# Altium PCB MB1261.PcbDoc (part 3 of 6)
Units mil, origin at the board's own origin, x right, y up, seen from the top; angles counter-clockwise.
Board outline 5119.1 x 2638.79 mil, 6 copper layers (TOP, L2_GND, L3_SIG, L4_VCC, L5_GND, BOTTOM), stack 61 mil thick; 336 components, 316 nets, 1358 pads, 871 vias.
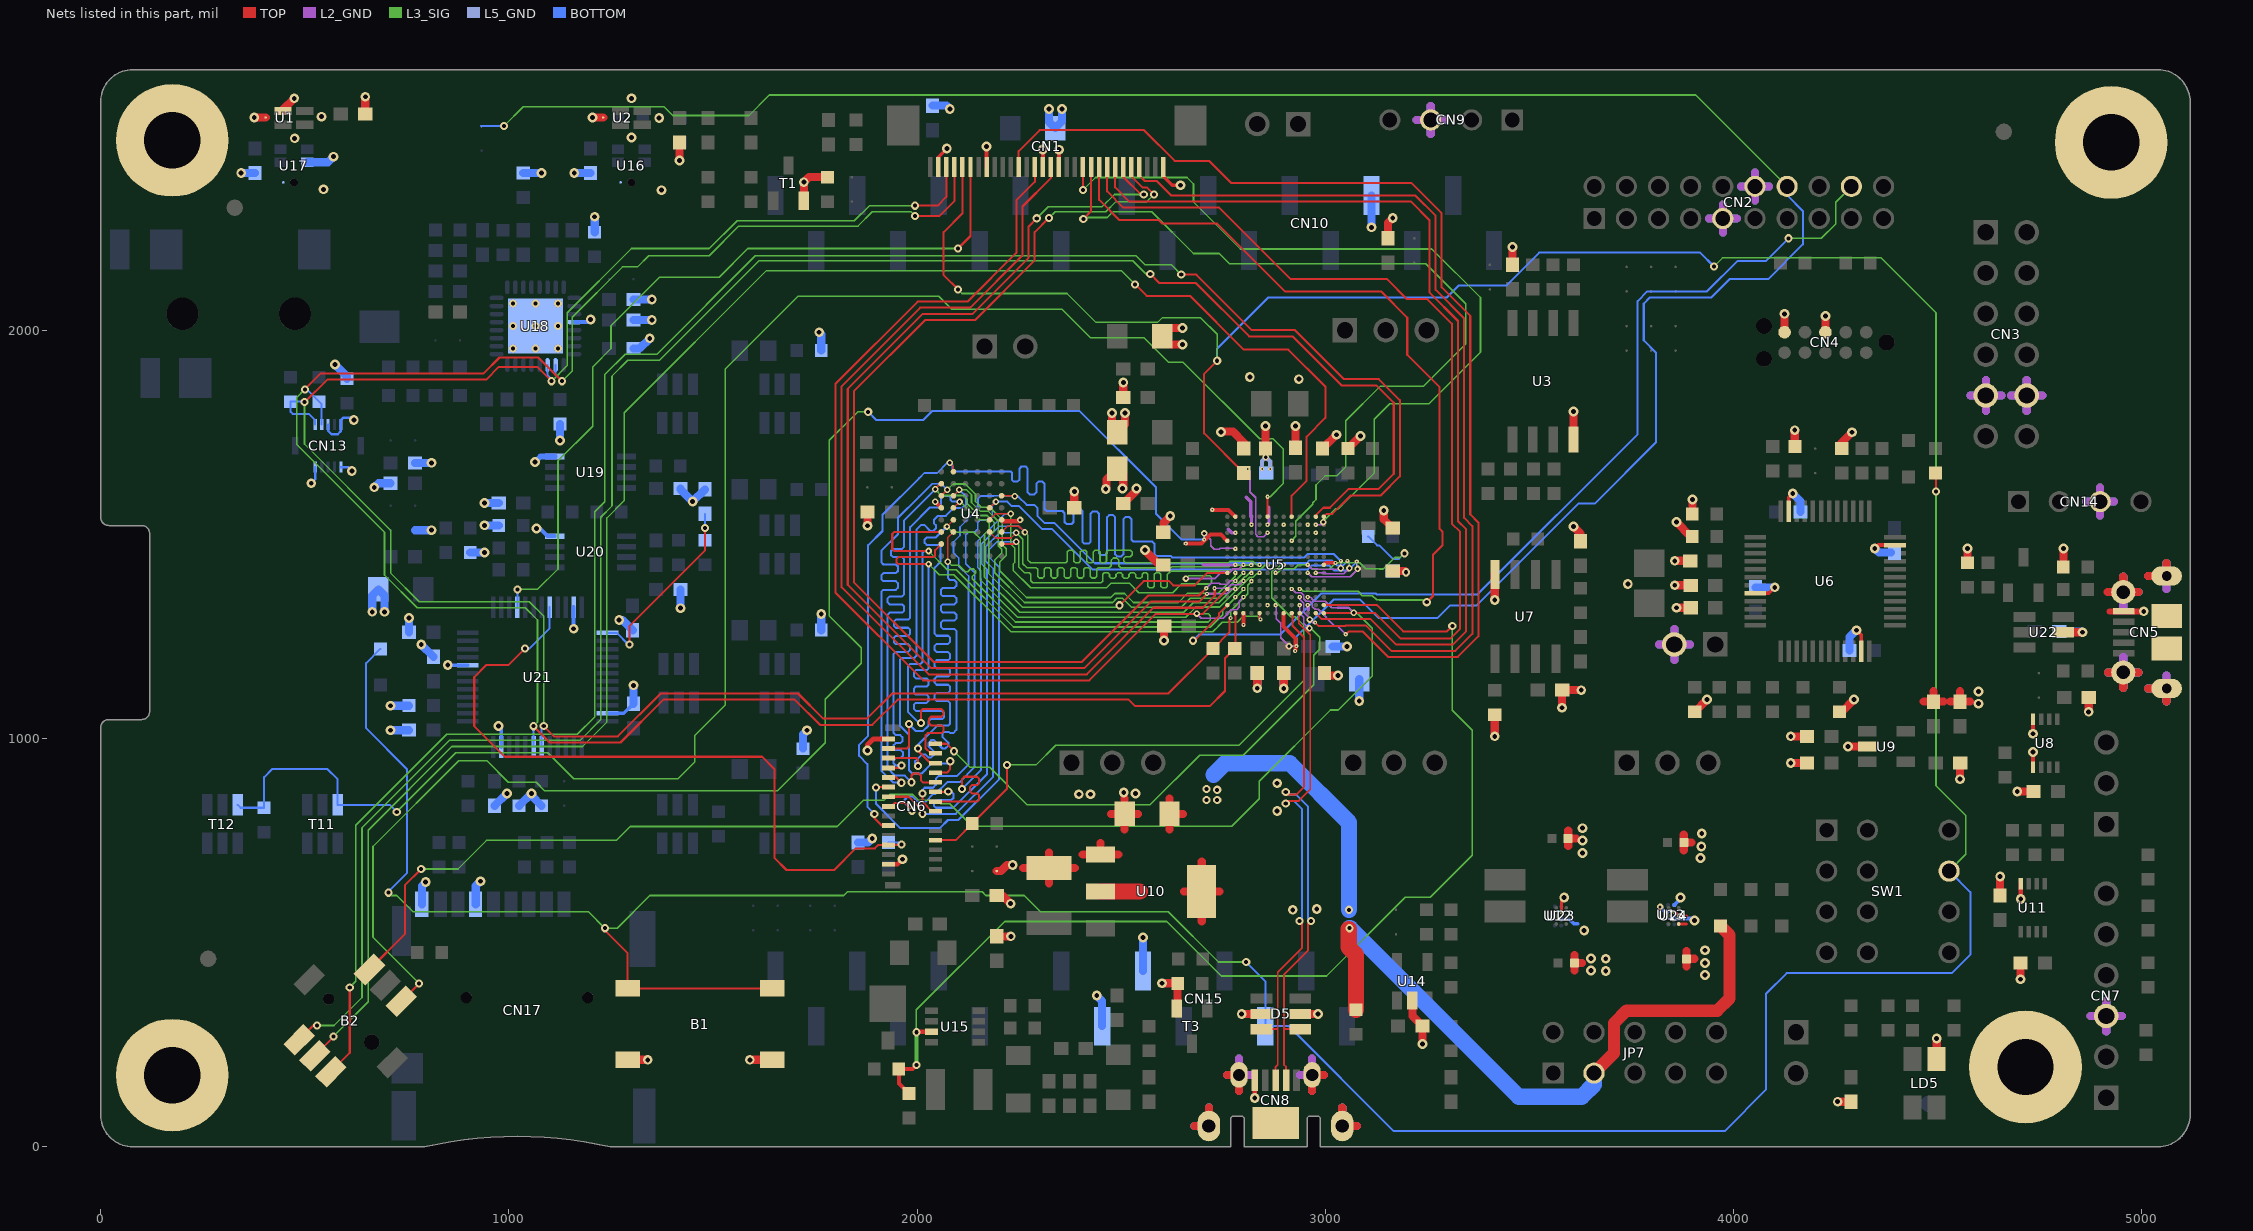
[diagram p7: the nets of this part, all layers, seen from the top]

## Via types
v1: diameter 20, hole 10, TOP to BOTTOM, tented both sides, 317 vias
v2: diameter 24, hole 12, TOP to BOTTOM, tented both sides, 289 vias
v3: diameter 10, hole 4, TOP to L2_GND, tented both sides, 76 vias
v4: diameter 10, hole 4, TOP to L3_SIG, tented both sides, 63 vias
v5: diameter 16, hole 8, L2_GND to L5_GND, tented both sides, 52 vias
v6: diameter 16, hole 8, TOP to BOTTOM, tented both sides, 43 vias
v7: diameter 10, hole 4, L5_GND to BOTTOM, tented both sides, 31 vias

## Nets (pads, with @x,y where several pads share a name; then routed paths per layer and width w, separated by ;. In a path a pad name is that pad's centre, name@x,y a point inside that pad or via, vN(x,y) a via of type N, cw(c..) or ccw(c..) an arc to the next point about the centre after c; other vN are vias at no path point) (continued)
D2: CN6.16 U4.C6 U5.B8 | length 2050.4
  TOP w4: U4.C6@2206.92,1594.29 2237.71,1594.29 v6(2239,1593)
  TOP w5: v1(2013.44,865) 2013.44,844.03 2035.95,821.52 CN6.16@2044.44,821.52
  L2_GND w3.5: v3(2976.53,1405.31) 2999.69,1405.31 3001.94,1403.06 3025.94,1403.06 3026,1403 3045,1403 v5(3059,1417)
  L5_GND w3.5: v7(3054,1434.84) 3058,1430.84 3058,1418 v5(3059,1417)
  BOTTOM w4: 2126,1390 2126,1398 2102,1422 2102,1442 2089,1455 2089,1481 2105,1497 2105,1518 2149,1562 2149,1586.9 2156,1593.9 2187.1,1593.9 2187.2,1594 2238,1594 v6(2239,1593)
  BOTTOM w5: v1(2013.44,865) 2013.44,873.81 2018.63,879 2038.78,879 2046,886.22 2046,901 2052.98,907.98 2097.76,907.98 2126,936.22 2126,1390 ; v6(2239,1593) 2240,1592 2248,1592 2268,1572 2287,1572 2294.5,1564.5 2294.5,1545.5 2312.5,1527.5 2336.72,1527.5 2435.22,1429 2954,1429 2961,1436 3016,1436 3029,1423 3042.16,1423 v7(3054,1434.84)
D3: CN6.15 U4.D5 U5.C8 | length 2179.3
  TOP w4: U4.D5@2177.39,1564.76 2177.76,1564.76 v6(2193,1580)
  TOP w5: CN6.15@1930.26,833.33 1936.38,833.33 1945,841.95 1969.53,841.95 1987.04,824.44 v1(1987.04,822.88)
  L2_GND w3.5: v3(2956.84,1405.31) 2966.59,1395.56 3022.83,1395.56 3022.89,1395.5 3060.49,1395.5 3079,1414 v5(3079,1415)
  L5_GND w3.5: v7(3076.89,1432.88) 3076.89,1416.11 3079,1414 v5(3079,1415)
  BOTTOM w4: 2141,1390 2141,1406 2119,1428 2119,1498 2126,1505 2141,1505 2148,1512 2148,1528 2155,1535 2177,1535 2184,1542 2184,1571 v6(2193,1580)
  BOTTOM w5: v1(1987.04,822.88) 1987.04,823.96 1969,842 1969,849 1978,858 1988,858 2001,845 2020.7,845 2039.7,864 2045,864 2073.98,892.98 2103.98,892.98 2141,930 2141,1390 ; v6(2193,1580) 2221,1580 2232,1569 2249.78,1569 2306.28,1512.5 2330.5,1512.5 2429,1414 2957,1414 2967,1424 3009,1424 3022,1411 3055,1411 v7@3076.77,1432.77 ; v7@3076.78,1432.77 v7(3076.89,1432.88)
D4: CN6.14 U4.E5 U5.L7 | length 1968
  TOP w4: U4.E5@2177.39,1535.24 2192.15,1550 v6(2229,1550)
  TOP w5: CN6.14@2044.44,845.14 2147,845.14 2152,850.14 2152,860.32 2147,865.32 2134,865.32 2129,870.32 2129,880.32 2134,885.32 2147,885.32 2152,890.32 2152,901 2147,906 2115.12,906 2110.12,901 v1(2110.12,876.26)
  L2_GND w3.5: 2766,1407.5 2773.75,1415.25 2789.61,1415.25 v3(2799.36,1425)
  L2_GND w5: v5(2658.48,1391.52) 2729.02,1391.52 2745,1407.5 2766,1407.5
  L3_SIG w4: v6(2229,1550) 2229,1476.2 2239,1466.2 2239,1431 2235,1427 2235,1412 2278,1369 2464,1369 2475,1380 2519.98,1380 2542.98,1357 2626,1357 2647.25,1378.25 2718.25,1378.25 2721,1381 2721,1394.72 2717.39,1398.33 2665.29,1398.33 v5(2658.48,1391.52)
  BOTTOM w4: 2156,1390 2156,1411 2148,1419 2148,1483 2215,1550 v6(2229,1550)
  BOTTOM w5: v1(2110.12,876.26) 2156,922.14 2156,1390
D5: CN6.13 U4.F5 U5.K7 | length 1940.2
  TOP w4: U4.F5@2177.39,1505.71 2192.1,1491 2230,1491 v6(2243,1504)
  TOP w5: CN6.13@1930.26,856.95 1979.3,856.95 2006.62,829.63 2006.62,822.23 v1(2013.45,815.4)
  L3_SIG w4: v6(2243,1504) 2259,1488 2259,1428 2269,1418 2291.08,1418 2295.08,1414 2295.08,1397 2299.08,1393 2307.08,1393 2311.08,1397 2311.08,1414 2315.08,1418 2323.95,1418 2327.95,1414 2327.95,1397 2331.95,1393 2339.95,1393 2343.95,1397 2343.95,1414 2347.95,1418 2355.95,1418 2359.95,1414 2359.95,1397 2363.95,1393 2371.95,1393 2375.95,1397 2375.95,1414 2379.95,1418 2387.95,1418 2391.95,1414 2391.95,1397 2395.95,1393 2403.95,1393 2407.95,1397 2407.95,1414 2411.95,1418 2419.95,1418 2423.95,1414 2423.95,1397 2427.95,1393 2435.95,1393 2439.95,1397 2439.95,1414 2443.95,1418 2470.76,1418 2475.76,1423 2475.76,1437 2480.76,1442 2489,1442 2494,1437 2494,1423 2499,1418 2622.08,1418 2624.08,1420 2764,1420 2768.3,1424.3 v4(2817.7,1424.3)
  BOTTOM w4: 2186,1390 2186,1416 2168,1434 2168,1470 2202,1504 v6(2243,1504)
  BOTTOM w5: v1(2013.45,815.4) 2013.85,815 2094.84,815 2186,906.16 2186,1390
D6: CN6.12 U4.F6 U5.J7 | length 1947.9
  TOP w4: U4.F6@2206.92,1505.71 2221.21,1520 2249.03,1520 v6@2260,1509.03
  TOP w5: CN6.12@2044.44,868.76 2075.23,868.76 v1(2076.16,869.69) ; v6@2260,1509.03 v6(2263.98,1505.05)
  L3_SIG w3.5: 2797,1434 2812.91,1434 2812.96,1434.05 2822.48,1434.05 2831.53,1425 v4(2838.73,1425)
  L3_SIG w4: v6(2263.98,1505.05) 2271,1498.03 2271,1437 2278,1430 2363.76,1430 2367.76,1434 2367.76,1457 2371.76,1461 2379.76,1461 2383.76,1457 2383.76,1434 2387.76,1430 2395.76,1430 2399.76,1434 2399.76,1457 2403.76,1461 2411.76,1461 2415.76,1457 2415.76,1434 2419.76,1430 2427.76,1430 2431.76,1434 2431.76,1457 2435.76,1461 2443.76,1461 2447.76,1457 2447.76,1434 2451.76,1430 2459.76,1430 2463.76,1434 2463.76,1457 2467.76,1461 2522.36,1461 2527,1456.36 2527,1449.8 2522.36,1445.16 2510.44,1445.16 2506,1440.72 2506,1434.44 2510.44,1430 2762.68,1430 2766.68,1434 2797,1434
  BOTTOM w4: 2171,1390 2171,1414 2158,1427 2158,1477 2201,1520 2249.03,1520 v6@2260,1509.03
  BOTTOM w5: v1(2076.16,869.69) 2084,869.69 2089,864.69 2089,854 2084,849 2045.92,849 2040.92,844 2040.92,835 2045.92,830 2088.62,830 2171,912.38 2171,1390 ; v6@2260,1509.03 v6(2263.98,1505.05)
D7: CN6.11 U4.G6 U5.H7 | length 2046.5
  TOP w4: U4.G6@2206.92,1476.18 2237.18,1476.18 v6(2243,1482)
  TOP w5: v1(1899.26,880) 1899.83,880.57 CN6.11@1930.26,880.57
  L3_SIG w3.5: 2617.1,1406 2621.1,1410 2767,1410 2773,1416 2811.51,1416 2812.96,1414.55 2821.04,1414.55 2821.55,1415.06 2843.06,1415.06 2853,1425 v4(2858.41,1425)
  L3_SIG w4: v6(2243,1482) 2249,1476 2249,1420 2263,1406 2274.32,1406 2278.32,1402 2278.32,1386 2283.32,1381 2450.32,1381 2454.32,1385 2454.32,1402 2458.32,1406 2467.12,1406 2471.12,1402 2471.12,1396 2475.12,1392 2483.12,1392 2487.12,1396 2487.12,1401.31 2491.81,1406 2498.43,1406 2503.12,1401.31 2503.12,1396 2507.12,1392 2515.12,1392 2519.12,1396 2519.12,1402 2523.12,1406 2531.12,1406 2535.12,1402 2535.12,1396 2539.12,1392 2547.12,1392 2551.12,1396 2551.12,1402 2555.12,1406 2561.1,1406 2565.1,1402 2565.1,1373 2569.1,1369 2577.1,1369 2581.1,1373 2581.1,1402 2585.1,1406 2593.1,1406 2597.1,1402 2597.1,1373 2601.1,1369 2609.1,1369 2613.1,1373 2613.1,1402 2617.1,1406
  BOTTOM w4: 2201,1390 2201,1419 2177,1443 2177,1463.5 2195.5,1482 v6(2243,1482)
  BOTTOM w5: v1(1899.26,880) 1899.26,839.74 1959,780 2055.48,780 2075.48,800 2101.06,800 2201,899.94 2201,1390
D8: CN6.10 U4.B1 U5.N8 | length 2036.8
  TOP w5: v1(1986.1,892.44) 1986.1,909 1991.1,914 2004,914 2009,909 2009,897.39 2014,892.39 CN6.10@2044.44,892.39 ; v6(2044,1610) 2044,1611.36 2056.46,1623.82 U4.B1@2059.28,1623.82 ; v1(2496,1326) 2555,1385 2617.1,1385 2627.1,1375 2680,1375 2710.31,1405.31 U5.N8@2759.99,1405.31
  L3_SIG w4: v6(2044,1610) 2059,1595 2114.64,1595 2123,1586.64 2123,1575 2152,1546 2172,1546 2189,1529 2189,1509 2175,1495 2175,1404 2258,1321 2491,1321 v1(2496,1326)
  BOTTOM w4: 2005,1571 v6(2044,1610)
  BOTTOM w5: v1(1986.1,892.44) 1969.66,908.88 1945.78,908.88 1927.5,927.16 1927.5,1303.03 1932.5,1308.03 1963,1308.03 1968,1313.03 1968,1323.03 1963,1328.03 1932.5,1328.03 1927.5,1333.03 1927.5,1343.03 1932.5,1348.03 1963,1348.03 1968,1353.03 1968,1439.06 1963,1444.06 1941,1444.06 1936,1449.06 1936,1459.06 1941,1464.06 1963,1464.06 1968,1469.06 1968,1534 2005,1571
D9: CN6.9 U4.C1 U5.M8 | length 2029.8
  TOP w4: U4.C1@2059.28,1594.29 v6(2074,1609.01)
  TOP w5: CN6.9@1930.26,904.2 1948.3,904.2 v1(1961.12,891.38)
  L3_SIG w3.5: 2662,1355 2738,1355 2779.67,1396.67 v4(2779.67,1405.31)
  L3_SIG w4: v6(2074,1609.01) 2087.99,1623 2118,1623 2143,1598 2143,1580.1 2157.2,1565.9 2178.1,1565.9 2208,1536 2208,1474.56 2218,1464.56 2218,1448 2202,1432 2202,1410.96 2267.96,1345 2473.96,1345 2483.96,1355 2508.03,1355 2530.03,1333 2640,1333 2662,1355
  BOTTOM w4: 2005,1592.22 2036.78,1624 2059.01,1624 v6(2074,1609.01)
  BOTTOM w5: v1(1961.12,891.38) 1942.06,891.38 1912.5,920.94 1912.5,1359 1917.5,1364 1948,1364 1953,1369 1953,1380 1948,1385 1917.5,1385 1912.5,1390 1912.5,1400 1917.5,1405 1948,1405 1953,1410 1953,1421 1948,1426 1917.5,1426 1912.5,1431 1912.5,1459.5 1953,1500 1953,1540.22 2005,1592.22
D10: CN6.8 U4.C2 U5.L8 | length 2014.5
  TOP w4: U4.C2@2088.81,1594.29 2102,1607.48 2102,1608 v6(2103,1609)
  TOP w5: CN6.8@2044.44,916.01 2073.01,916.01 2081,924 v1(2081,944)
  L3_SIG w3.5: 2669,1343 2737.05,1343 v4(2799.36,1405.31)
  L3_SIG w4: v6(2103,1609) 2120.68,1609 2133,1596.68 2133,1578 2155,1556 2175,1556 2199,1532 2199,1471.68 2207,1463.68 2207,1453.9 2190,1436.9 2190,1405.98 2262.98,1333 2478.95,1333 2488.95,1343 2503.05,1343 2525.05,1321 2647,1321 2669,1343
  BOTTOM w5: v1(2081,944) 2075,938 2035,938 2011,914 1988,914 1980,922 1980,1009 1957.5,1031.5 1957.5,1192 1962.5,1197 1993,1197 1998,1202 1998,1511 2009.99,1522.99 2017.07,1522.99 2031.99,1508.07 2039.07,1508.07 2046.14,1515.14 2046.14,1522.22 2041,1527.36 2041,1535 2051,1545 2070,1545 2089.5,1564.5 2110.5,1564.5 2120,1574 2120,1592 v6(2103,1609)
D11: CN6.7 U4.D2 U5.K8 | length 2022.5
  TOP w4: U4.D2@2088.81,1564.76 v6(2104,1580)
  TOP w5: CN6.7@1930.26,927.82 1955.14,927.82 v1(1961.26,933.94)
  L3_SIG w3.5: 2617.1,1309 2653,1309 2676,1332 2739,1332 2802.56,1395.56 2804.7,1395.56 2813.94,1404.8 v4(2818,1404.8)
  L3_SIG w4: v6(2104,1580) 2106,1580 2150,1536 2167,1536 2177,1526 2177,1512 2165,1500 2165,1394.96 2250.96,1309 2617.1,1309
  BOTTOM w5: v1(1961.26,933.94) 1947.06,933.94 1942.5,938.5 1942.5,947 1947.5,952 1960,952 1965,957 1965,966 1960,971 1947.5,971 1942.5,976 1942.5,983.14 1947.5,988.14 1959,988.14 1964,993.14 1964,1003.14 1959,1008.14 1947.5,1008.14 1942.5,1013.14 1942.5,1207 1947.5,1212 1978,1212 1983,1217 1983,1225.97 1978,1230.97 1948,1230.97 1943,1235.97 1943,1245.97 1948,1250.97 1978,1250.97 1983,1255.97 1983,1265.97 1978,1270.97 1948,1270.97 1943,1275.97 1943,1285.97 1948,1290.97 1978,1290.97 1983,1295.97 1983,1517.22 2031.28,1565.5 2052.5,1565.5 2058.5,1571.5 2058.5,1589.5 2063,1594 2078,1594 2082,1590 2082,1584 2086,1580 v6(2104,1580)
D12: CN6.6 U4.E2 U5.J8 | length 2001.6
  TOP w4: v6(2073,1519) U4.E2@2089,1535 ; U4.E2@2088.81,1535.24 U4.E2@2089,1535.05
  TOP w5: v1(2002,975.38) 2002,970 2032.37,939.63 CN6.6@2044.44,939.63
  L3_SIG w4: v6(2073,1519) 2087,1505 2138.8,1505 2155,1488.8 2155,1387.98 2245.98,1297 2657.91,1297 2682.91,1322 2741.27,1322 2795.21,1375.94 2796.05,1375.94 2814.85,1394.74 2822.76,1394.74 2831.15,1403.13 2836.55,1403.13 v4(2838.73,1405.31)
  BOTTOM w5: v1(2002,975.38) 2002,984.41 2049,1031.41 2076,1031.41 2081,1036.41 2081,1086.41 2076,1091.41 2048,1091.41 2043,1096.41 2043,1106.41 2048,1111.41 2076,1111.41 2081,1116.41 2081,1126.41 2076,1131.41 2048,1131.41 2043,1136.41 2043,1146.41 2048,1151.41 2076,1151.41 2081,1156.41 2081,1166.41 2076,1171.41 2048,1171.41 2043,1176.41 2043,1186.41 2048,1191.41 2076,1191.41 2081,1196.41 2081,1206.41 2076,1211.41 2048,1211.41 2043,1216.41 2043,1226.41 2048,1231.41 2076,1231.41 2081,1236.41 2081,1246.41 2076,1251.41 2048,1251.41 2043,1256.41 2043,1418.08 2057,1432.08 2057,1469 2052,1474 2023,1474 2018,1479 2018,1487 2023,1492 2046,1492 v6(2073,1519)
D13: CN6.5 U4.F2 U5.L11 | length 1964.6
  TOP w4: v6(2075,1433) 2075,1491.9 U4.F2@2088.81,1505.71
  TOP w5: CN6.5@1930.26,951.44 1998.43,951.44 2001.88,947.99 v1(2001.88,932)
  L2_GND w3.5: v5(2685,1305.7) 2696.3,1294.4 2749.4,1294.4 2770,1315 2782.41,1315 2789.42,1322.01 2789.42,1336.31 v3(2799.36,1346.25)
  L3_SIG w4: v6(2075,1433) 2084,1424 2102,1424 2118.14,1407.86 2123.8,1407.86 2131.64,1415.7 2137.3,1415.7 2142.96,1410.04 2142.96,1404.38 2135.12,1396.54 2135.12,1390.88 2241,1285 2713,1285 2718,1290 2718,1300.7 2713,1305.7 v5(2685,1305.7)
  BOTTOM w5: v1(2001.88,932) 1995,938.88 1995,944 2012.04,961.04 2019.49,961.04 2027.22,953.29 2034.28,953.29 2041.4,960.4 2041.4,967.44 2027.44,981.38 2027.44,988.44 2034.54,995.54 2041.6,995.54 2062.02,975.1 2069.09,975.1 2076.2,982.19 2076.2,989.24 2061.94,1003.49 2061.94,1011 2066.94,1016 2077.72,1016 2081.01,1012.71 2088.07,1012.71 2096,1020.64 2096,1263.43 2091,1268.43 2063,1268.43 2058,1273.43 2058,1283.43 2063,1288.43 2091,1288.43 2096,1293.43 2096,1303.43 2091,1308.43 2063,1308.43 2058,1313.43 2058,1323.43 2063,1328.43 2091,1328.43 2096,1333.43 2096,1343.43 2091,1348.43 2063,1348.43 2058,1353.43 2058,1363.43 2063,1368.43 2091,1368.43 2096,1373.43 2096,1383 2091,1388 2080,1388 2075,1393 v6(2075,1433)
D14: CN6.4 U4.F1 U5.L10 | length 1931.6
  TOP w5: v1(2009,1037.38) 2009,1067 2014,1072 2059,1072 2064,1067 2064,1058 2059,1053 2034,1053 2029,1048 2029,1037 2034,1032 2060,1032 2065,1027 2065,1018 2060,1013 2025.5,1013 2020.5,1008 2020.5,975.88 2033.13,963.25 CN6.4@2044.44,963.25 ; v6(2028,1459) 1944,1459 1939,1464 1939,1500.71 1944,1505.71 U4.F1@2059.28,1505.71
  L3_SIG w3.5: 2721,1275 2749,1303 2749,1314 2799.36,1364.36 v4(2799.36,1365.94)
  L3_SIG w4: v6(2028,1459) 2074,1413 2096,1413 2236,1273 2719,1273 2721,1275
  BOTTOM w5: v1(2009,1037.38) 2004.62,1037.38 1977,1065 1977,1177 1982,1182 2008,1182 2013,1187 2013,1455 2017,1459 v6(2028,1459)
D15: CN6.3 U4.G1 U5.J13 | length 1952.4
  TOP w5: CN6.3@1930.26,975.06 1975,975.06 1980,980.06 v1(1980,1035) ; v6(2028,1427) 1953.98,1427 1949,1431.98 1949,1439.02 1953.98,1444 2040,1444 2044,1448 2044,1460.9 U4.G1@2059.28,1476.18 ; U5.J13@2838.73,1306.89 2838.73,1294.14 v4(2841.25,1291.62)
  L3_SIG w3.5: 2738,1275 2747,1284 2784,1284 2799,1299 2833.87,1299 v4(2841.25,1291.62)
  L3_SIG w4: v6(2028,1427) 2054,1401 2090,1401 2230,1261 2724,1261 2738,1275
  BOTTOM w5: v1(1980,1035) 1997.19,1017.81 2014.18,1017.81 2028,1031.63 2028,1042.17 2033,1047.17 2061,1047.17 2066,1052.17 2066,1062.17 2061,1067.17 1997,1067.17 1992,1072.17 1992,1082 1997,1087 2023,1087 2028,1092 2028,1102 2023,1107 1997,1107 1992,1112 1992,1122 1997,1127 2023,1127 2028,1132 2028,1142 2023,1147 1997,1147 1992,1152 1992,1162 1997,1167 2023,1167 2028,1172 v6(2028,1427)
D_N: CN8.2 D5.4 U5.E13 | length 1305.9
  TOP w4.8: v1(2903,868.5) 2909.5,862 2928.78,862 2948,881.22 2948,1247.13 2919.81,1275.32 2919.81,1304.55 U5.E13@2917.47,1306.89 ; CN8.2@2903.69,162.8 2903.69,195.3 2898.39,200.6 2898.39,287.6 ; D5.4@2938.13,287.6 2898.39,287.6 ; v1(2964.5,552.69) 2958,546.19 2958,481 2898.39,421.39 2898.39,287.6
  BOTTOM w4.8: v1(2903,868.5) 2909.5,862 2929,862 2958,833 2958,559.19 v1(2964.5,552.69)
D_P: CN8.3 D5.3 U5.D13 | length 1305.9
  TOP w4.8: D5.3@2843.65,287.6 2883.39,287.6 ; CN8.3@2878.1,162.8 2878.1,195.31 2883.39,200.6 2883.39,287.6 ; v1(2903,840.5) 2909.5,847 2935,847 2963,875 2963,1253.35 2934.81,1281.54 2934.81,1304.54 U5.D13@2937.16,1306.89 ; v1(2936.5,552.69) 2943,546.19 2943,487.22 2883.39,427.61 2883.39,287.6
  BOTTOM w4.8: v1(2903,840.5) 2909.5,847 2922.78,847 2943,826.78 2943,559.19 v1(2936.5,552.69)
DATIN3: CN2.17 SB17.2 U5.G12 | length 5571.4
  L2_GND w3.5: v3(2878.1,1326.57) 2879.1,1325.57 2879.1,1293.19 2890.7,1281.59 2890.7,1247.01 2910.91,1226.8 v5(2910.91,1225.9)
  L3_SIG w4: v1(988,2500) 1035,2547 1380,2547 1401,2526 1588,2526 1638,2576 3907.37,2576 CN2.17@4131.21,2352.16
  L5_GND w3.5: v5(2910.91,1225.9) v7(2929.1,1225.9)
  BOTTOM w5: SB17.2@933.1,2500 v1(988,2500) ; v7(2929.1,1225.9) 2929.1,1249.1 3020,1340 3085,1340 3130,1295 3275,1295 3305,1325 3370,1325 3620,1575 3660,1575 3810,1725 3810,1945 3780,1975 3780,2065 3795,2080 3945,2080 3990,2125 4085,2125 4170,2210 4170,2292 4131.21,2330.79 CN2.17@4131.21,2352.16
DCMI_CLK: R100.2 U5.G8 | length 473.5
  L3_SIG w3.5: v4(2878.1,1405.31) 2883.31,1405.31 2893.06,1415.06 2923.57,1415.06 2933.51,1425 2957,1425 2967.75,1414.25 3009.25,1414.25 3025,1430 3084.39,1430 3099.39,1415 3132,1415
  L3_SIG w4: 3132,1415 3141.98,1415 3169.98,1443 3183.08,1443 v1(3193.49,1453.41)
  BOTTOM w5: R100.2@3105,1495 3127,1473 3132.17,1473 3165.17,1440 3180.08,1440 v1(3193.49,1453.41)
DCMI_D0: CN1.4 U5.D11 | length 2363.3
  TOP w5: CN1.4@2544.04,2400 2544.04,2379.08 2558.12,2365 2587.5,2365 2622.5,2330 3220,2330 3270,2280 3270,2098.66 3340,2028.66 3340,1540 3360,1520 3360,1256.34 3318.16,1214.5 3161.51,1214.5 3099.1,1276.89 3050.67,1276.89 3048.78,1275 2983.45,1275 v3(2975,1283.45)
  L2_GND w3.5: v3(2937.16,1346.26) 2937.16,1340.36 2946.91,1330.61 2946.91,1322.53 2946.59,1322.21 2946.59,1312.23 2947,1311.82 2947,1309.5 2962,1294.5 v5(2962,1291) 2969.55,1283.45 v3(2975,1283.45)
DCMI_D1: CN1.5 U5.M9 | length 2639.7
  TOP w5: v1(2323,2275) 2288,2240 2288,2171 2142,2025 2020,2025 1845,1850 1845,1382.44 2040.44,1187 2403.22,1187 2566.22,1350 2690.5,1350 v3(2708.3,1367.8) ; CN1.5@2524.36,2400 2524.36,2377.54 2551.9,2350 2562.55,2350 v1(2580.05,2332.5)
  L2_GND w3.5: v3(2708.3,1367.8) 2721.05,1380.55 2739.45,1380.55 2742,1378 2759.37,1378 2767,1385.63 v3(2779.67,1385.63)
  L3_SIG w4: v1(2323,2275) 2338,2290 2462,2290 2487,2315 2562.55,2315 v1(2580.05,2332.5)
DCMI_D2: CN1.6 U5.M10 | length 2654.7
  TOP w5: v1(2293,2274) 2273,2254 2273,2177.22 2135.78,2040 2013.78,2040 1830,1856.22 1830,1376.22 2034.22,1172 2409.44,1172 2572.44,1335 2691.15,1335 v3(2710.05,1353.9) ; CN1.6@2504.67,2400 2504.67,2375.33 2547.5,2332.5 v1(2555.05,2332.5)
  L2_GND w3.5: 2725.7,1354.3 2758.36,1354.3 2770,1365.94 v3(2779.67,1365.94)
  L2_GND w5: v3(2710.05,1353.9) 2710.45,1354.3 2725.7,1354.3
  L3_SIG w4: v1(2293,2274) 2321,2302 2453,2302 2483.5,2332.5 v1(2555.05,2332.5)
DCMI_D3: CN1.7 U5.B13 | length 2312.1
  TOP w5: CN1.7@2484.99,2400 2484.99,2350 2519.99,2315 3210,2315 3255,2270 3255,2092.44 3325,2022.44 3325,1532.13 3345,1512.13 3345,1262.56 3311.94,1229.5 3173.5,1229.5 3111.11,1291.89 2991.53,1291.89 U5.B13@2976.53,1306.89
DCMI_D4: CN1.8 U5.A13 | length 2164.2
  TOP w5: CN1.8@2465.3,2400 2465.3,2340 2505.3,2300 2740,2300 2915,2125 3151.22,2125 3200,2076.22 3250,2076.22 3310,2016.22 3310,1525.91 3330,1505.91 3330,1268.78 3305.72,1244.5 3184.4,1244.5 3122,1306.9 3105.69,1306.9 U5.A13@2996.21,1306.89
DCMI_D5: CN1.9 U5.D10 | length 2028.7
  TOP w5: CN1.9@2445.62,2400 2445.62,2319.38 2495,2270 2592,2270 2601,2261 2734.78,2261 2900.78,2095 3136.22,2095 3200.6,2030.62 3200.6,1939.4 3280,1860 3280,1513.47 3287,1506.47 3287,1473.22 3263.7,1449.92 3263.7,1348.7 3248.62,1333.62 v1(3248.39,1333.62)
  L3_SIG w3.5: v4(2937.16,1365.94) 2940,1365.94 2945.94,1360 3080,1360 3090,1350 3115,1350 3126,1339 3132,1339
  L3_SIG w4: 3132,1339 3242,1339 3247.38,1333.62 v1(3248.39,1333.62)
DCMI_D6: CN1.10 U5.E4 | length 2010.2
  TOP w5: v1(2407,2272) 2425.93,2290.93 CN1.10@2425.93,2400
  L3_SIG w3.5: v4(2917.47,1484.06) 2928,1494.59 2928,1532 2969.1,1573.1 2969.1,1577.08
  L3_SIG w4: v1(2407,2272) 2411,2276 2466,2276 2480,2290 2575,2290 2677,2188 2740,2188 2765,2163 3246.06,2163 3344,2065.06 3344,1966 3241,1863 3135,1863 3050,1778 3050,1664.98 3028,1642.98 2999.12,1642.98 2977,1620.86 2977,1584.98 2969.1,1577.08
DCMI_D7: CN1.11 U5.B2 | length 1982.3
  TOP w5: v1(2406.25,2343) CN1.11@2406.25,2400
  L2_GND w3.5: v3(2976.53,1523.43) 2988.43,1523.43 v5(2995,1530)
  L3_SIG w3.5: v5(2995,1530) 2995,1531.98 3026.02,1563 3030,1563
  L3_SIG w4: v1(2406.25,2343) 2406.25,2343.25 2437,2374 2661,2374 2677,2358 2677,2314 2792,2199 3261,2199 3380,2080 3380,1946 3254,1820 3158,1820 3120.01,1782.01 3120.01,1649.98 3033.03,1563 3030,1563
DCMI_HSYNC: CN1.17 U5.N10 | length 2459.3
  TOP w5: CN1.17@2288.14,2400 2288.14,2363.14 2243,2318 2243,2189.66 2123.34,2070 2001.34,2070 1800,1868.66 1800,1356.51 2014.51,1142 2421.88,1142 2584.88,1305 2700,1305 2759.99,1364.99 U5.N10@2759.99,1365.94
DCMI_I2C2_SCL: CN1.28 CN13.5 R42.2 R88.2 U5.K9 U18.3 U21.42 | length 5386.1
  TOP w5: v1(499,1824) 500,1824 555,1879 944,1879 975,1910 1069.53,1910 v1(1104.53,1875) ; v1(1085.16,1029.97) 1110.13,1005 1266.92,1005 1371.92,1110 1708,1110 1769,1049 1878,1049 1939,1110 2615,1110 R42.2@2725,1220 2764.67,1259.67 2764.67,1291.49 v4(2767.92,1294.74) ; v1(1995,2305) 2050,2305 2071.6,2326.6 CN1.28@2071.6,2400
  L3_SIG w3.5: v4(2767.92,1294.74) 2767.92,1312.92 2809.29,1354.29 2809.29,1375.03 v4(2819,1384.74)
  L3_SIG w4: v1(499,1824) 499,1721 710,1510 710,1405 780,1335 1050,1335 1085.16,1299.84 v1(1085.16,1029.97) ; v1(1104.53,1875) 1143,1913.47 1143,2043 1300,2200 1491.02,2200 1559.02,2268 1846.02,2268 1883.02,2305 v1(1995,2305)
  BOTTOM w5: v1(499,1824) 500,1824 499,1825 R88.2@465,1825 465,1800 470,1795 510,1795 525.38,1779.62 CN13.5@525.38,1768.59 ; U21.42@1079.84,978.74 1079.84,1024.65 v1(1085.16,1029.97) ; U18.3@1094.53,1914.72 1094.53,1889.25 1104.53,1879.25 v1(1104.53,1875)
DCMI_I2C2_SDA: CN1.27 CN13.4 R43.2 R87.1 U5.M13 U18.2 U21.43 | length 5469.4
  TOP w5: v1(500,1855) 539,1894 937.78,1894 976.89,1933.11 1071.89,1933.11 v1(1130,1875) ; v1(1060.16,1029.84) 1100,990 1273.14,990 1378.14,1095 1700,1095 1762,1033 1890,1033 1952,1095 2518,1095 2534,1079 2717,1079 2754.05,1116.05 2754.05,1195.95 R43.2@2778.1,1220 2779.67,1221.57 U5.M13@2779.67,1306.89 ; v1(1995,2280) 2055,2280 2091.29,2316.29 CN1.27@2091.29,2400
  L3_SIG w4: v1(500,1855) 480,1835 480,1720 695,1505 695,1400 775,1320 1040,1320 1070,1290 1070,1039.68 v1(1060.16,1029.84) ; v1(1130,1875) 1155,1900 1155,2032 1278,2155 1315,2155 1342.5,2182.5 1490.5,2182.5 1563,2255 1855,2255 1890,2290 1985,2290 v1(1995,2280)
  BOTTOM w5: v1(500,1855) 505,1855 R87.1@535,1825 541.13,1818.87 CN13.4@541.13,1768.59 ; U21.43@1060.16,978.74 v1(1060.16,1029.84) ; U18.2@1114.21,1914.72 1114.21,1890.79 v1(1130,1875)
DCMI_NRST: B1.1 B1.4 C10.1 CN1.26 CN15.3 D6.2 R25.2 SW1.7 U5.H3 | length 11056.6
  TOP w5: v1(1235,535) 1235,530 1290.93,474.07 B1.4@1290.93,387.5 B1.1@1645.27,387.5 ; v1(2100,2100) 2065,2135 2065,2240 2110.97,2285.97 CN1.26@2110.97,2400 ; v1(2735,1925) 2703,1893 2703,1747 C10.1@2800,1650 v3(2810,1660) ; R25.2@4495,1650 4496,1649 v1(4496,1605)
  L2_GND w3.5: 2828.98,1527.47 2828.98,1500.12 2834.9,1494.2 2848.87,1494.2 v3(2858.41,1503.74) ; 2829,1527.49 2829,1590
  L2_GND w5: v3(2810,1660) 2815,1655 2815,1604 2829,1590
  L3_SIG w4: v1(705,622) 712,615 725,615 765,575 1195,575 v1(1235,535) 1265,535 1345,615 1820.2,615 1829.2,624 2159.29,624 2168.29,615 2262,615 2302,575 2615,575 2738,452 v1(2806,452) ; v1(2100,2100) 2110,2090 2367,2090 2438,2019 2589,2019 2600,2030 2695,2030 2735,1990 v1(2735,1925) ; v1(3952,2156) 3973,2177 4362,2177 4496,2043 v1(4496,1605) 4496,884 4569,811 4569,715.9 SW1.7@4528.1,675
  BOTTOM w5: D6.2@685,1219.29 650,1184.29 650,1025 750,925 750,670 705,625 v1(705,622) ; v1(2735,1925) 2735,1955 2860,2080 3297,2080 3326.11,2109.11 3442.89,2109.11 3523.78,2190 3918,2190 v1(3952,2156) ; v1(2806,452) 2853.1,404.9 CN15.3@2853.1,295 2911,295 3168,38 3978,38 4080,140 4080,375 4130,425 4535,425 4580,470 4580,623.1 SW1.7@4528.1,675
DCMI_PIXCK: CN1.15 U5.L9 | length 2493.1
  TOP w5: CN1.15@2327.51,2400 2327.51,2372.51 2258,2303 2258,2183.44 2129.56,2055 2007.56,2055 1815,1862.44 1815,1370 2028,1157 2415.66,1157 2578.66,1320 2700,1320 2729,1349 2729,1367.1 v3(2728.3,1367.8)
  L2_GND w3.5: v3(2728.3,1367.8) 2759.92,1367.8 2768,1375.88 2789.62,1375.88 v3(2799.36,1385.63)
DCMI_PWR_EN: CN1.25 U21.16 | length 1954.5
  TOP w5: v1(2100,2200) 2130.66,2230.66 CN1.25@2130.66,2400
  L3_SIG w4: v1(1020.79,1365) 1070,1365 1120,1415 1120,1680 1205,1765 1205,1910 1250,1955 1250,2011 1369,2130 1515,2130 1585,2200 v1(2100,2200)
  BOTTOM w5: U21.16@1020.79,1321.26 v1(1020.79,1365)
DCMI_VSYNC: CN1.19 U5.E10 | length 2816.2
  TOP w5: CN1.19@2248.77,2400 2248.77,2438.77 2300,2490 2555.78,2490 2630.78,2415 2715,2415 2770,2360 3211.22,2360 3285,2286.22 3285,2104.88 3355,2034.88 3355,1548.78 3375,1528.78 3375,1250.12 3324.38,1199.5 3153.5,1199.5 3091.11,1261.89 3056.89,1261.89 v3(3050,1255)
  L2_GND w3.5: v3(2917.47,1365.94) 2927.22,1356.19 2941.2,1356.19 2947.09,1350.3 2947.09,1342.22 2952.8,1336.51 2961.59,1336.51 2968.25,1329.85 2968.25,1322.53 2974.78,1316 2982,1316 3023,1275 3030,1275
  L2_GND w5: 3030,1275 v3(3050,1255)
DFDATIN1: CN2.19 U5.N12 | length 2422.7
  TOP w5: v1(2675.73,1239.27) 2679.27,1239.27 2740,1300 2740,1306.58 U5.N12@2759.99,1326.57
  L3_SIG w4: v1(4135,2225) 4215,2225 4250,2260 4250,2313.47 CN2.19@4288.69,2352.16
  BOTTOM w5: v1(2675.73,1239.27) 2691.46,1255 2890,1255 2990,1355 3123.27,1355 3125.78,1352.49 3372.49,1352.49 3765,1745 3765,2071.22 3788.78,2095 3935,2095 4010,2170 4080,2170 v1(4135,2225)
E5V: C37.1 D2.1 JP7.3 R72.1 U10.2 U10.4 | length 2709
  TOP w20: 2618.1,776.98 C37.1@2618.1,815 ; 2618.1,853.02 C37.1@2618.1,815 ; 2651.12,815 C37.1@2618.1,815 ; 2653.6,625 U10.4@2697.12,625 ; 2697.12,551.98 U10.4@2697.12,625 ; 2697.12,698.02 U10.4@2697.12,625 ; 2740.64,625 U10.4@2697.12,625
  TOP w30: JP7.3@3658.1,180 3707,228.9 3707,302 3738,333 3960,333 3990,363 3990,518.55 D2.1@3967.84,540.71
  TOP w40: U10.2@2449.08,625 2545,625 ; v1@3057.1,533 3057.1,487.9 3075,470 R72.1@3075,335
  BOTTOM w40: 2726,911 2754,939 2913,939 3058,794 v1(3058,580) ; v1(3059.1,535) 3061,535 3474,122 3628.1,122 3658.1,152 JP7.3@3658.1,180
  other v1: 2708.95,849.02 2735,849 2735,874 2709,876
GND: B1.2 B1.3 C1.2 C2.2 C3.2 C4.2 C6.2 C7.2 C8.2 C9.1 C10.2 C11.1 C12.2 C13.2 C14.2 C15.2 C16.2 C17.2 C18.2 C19.1 C20.1 C21.2 C22.2 C23.1 C24.2 C25.2 C26.2 C27.2 C28.2 C29.1 C30.1 C31.2 C32.2 C33.2 C34.2 C35.2 C36.2 C37.2 C40.2 C41.2 C42.2 C43.2 C44.2 C45.2 C46.2 C51.1 C54.2 C60.2 C61.2 C62.2 C63.2 C71.1 C73.2 C74.2 C80.2 C81.2 C82.2 C83.1 C84.2 C85.1 C86.2 C87.2 C89.2 C90.2 C91.2 C92.2 C93.2 C94.2 C95.2 C96.2 C97.2 C98.2 C99.1 C100.2 C101.2 C102.2 C103.2 C104.2 C105.2 CN1.1 CN1.14 CN1.16 CN1.23 CN1.29 CN2.5 CN2.16 CN3.5 CN3.11 CN4.3 CN4.5 CN5.5 CN5.6 CN5.7 CN5.8 CN5.9 CN5.10 CN5.11 CN6.1 CN6.27 CN7.3 CN8.5 CN8.6 CN8.7 CN8.8 CN8.9 CN8.10 CN9.3 CN10.7 CN13.1 CN13.3 CN13.6 CN13.10 CN14.3 CN15.6 CN15.7 CN17.6 CN17.9 D5.2 D5.5 H1.1 H2.1 H3.1 H4.1 JP10.2 L4.1 LD5.1 LD8.2 R17.2 R20.1 R22.1 R30.1 R31.1 R33.1 R34.2 R48.1 R49.2 R50.1 R65.1 R80.1 R83.1 R84.1 R89.2 R91.1 R98.2 R104.2 R106.1 R109.1 R110.1 R112.2 R113.2 R124.2 SB15.1 SB22.1 T1.2 T3.2 U1.2 U1.5 U2.5 U3.4 U4.D1 U4.E6 U5.A7 U5.B3 U5.C2 U5.C12 U5.F2 U5.F13 U5.H2 U5.H12 U5.K2 U5.L13 U5.M1 U5.M3 U5.M7 U5.M11 U5.N4 U6.8 U6.23 U6.35 U6.47 U7.4 U8.4 U8.5 U9.2 U10.1 U11.4 U12.B2 U13.B2 U13.C1 U13.D2 U14.2 U16.3 U17.2 U17.3 U18.28 U18.33 U19.4 U20.4 U21.8 U21.23 U21.35 U21.47 U22.2 U23.D2 U24.A1 U24.C1 U24.D2 | length 13902.1
  TOP w7: U23.D2@3578.1,574.84 3578.1,603.1 v2(3585,610)
  TOP w8: U5.A7@2996.21,1425 3001.21,1430 v3(3025,1430) ; U24.D2@3853.1,574.84 3855.54,574.84 U24.C1@3865.38,565 3885,565 ; U24.A1@3865.38,545.31 3884.69,545.31
  TOP w9: CN1.29@2051.92,2400 2051.92,2423.76 2070,2441.84 2070,2442.2 v2(2072.69,2444.89) ; CN1.1@2603.1,2400 2603.1,2376.9 2625,2355 v2(2645,2355) ; U6.8@4052.84,1355.47 4086.47,1355.47 v2(4101,1370) ; U6.47@4135.52,1556.26 4135.52,1590.52 v2(4145,1600) ; v2(4301,1265) 4312.68,1253.32 U6.23@4312.68,1213.74 ; v2(4346,1465) 4354.58,1473.58 U6.35@4395.36,1473.58
  TOP w10: CN6.27@1930.26,691.6 1951.6,691.6 v2(1963.9,703.9) ; v6(2044,1580) U4.D1@2059.24,1564.76 ; CN1.23@2170.03,2400 v2(2170.03,2449.97) ; U4.E6@2206.92,1535.24 2210.16,1532 2248.76,1532 v6(2252,1535.24) ; CN1.16@2307.82,2400 v2(2307.82,2442.82) ; CN1.14@2347.19,2400 v2(2347.19,2442.19) ; v3(2658,1477) 2697,1477 2719,1499 2744,1499 2758.94,1484.06 U5.N4@2759.99,1484.06 ; v3(2723,1560) 2724,1559 2763.2,1559 2779.09,1543.11 U5.M1@2779.67,1543.11 ; v3(2799.36,1278) U5.L13@2799.36,1306.89 ; U5.F13@2897.79,1306.89 2897.79,1274.21 2927,1245 2927,1215 v3(2926,1214) ; v2(4703.57,606.43) U11.4@4703.57,644.06 ; U8.5@4733.57,928.94 v2(4733.57,966.43) ; v2(4733.57,1011.43) U8.4@4733.57,1047.06
  TOP w12: v2(1878,970) 1878,983.68 1893,998.68 CN6.1@1930.26,998.68 ; v2(2826.92,119.3) CN8.5@2826.92,162.8
  TOP w15: 4921.18,1311.18 CN5.5@4955.7,1311.18 v2(5005,1311.18)
  TOP w20: v2(376,2521) U1.5@404.1,2521 ; U1.2@446.53,2536.73 446.53,2540.53 v2(474,2568) ; C1.2@648.1,2530 v2(648.1,2571.9) ; v2(1205,2521) U2.5@1230.79,2521 ; B1.3@1290.93,212.5 v2(1340,212.5) ; v2(1418.1,2415.9) C2.2@1418.1,2460 ; v2(1590,212.5) B1.2@1645.27,212.5 ; T1.2@1722.4,2316.69 v2(1722.4,2362.6) 1734.8,2375 R124.2@1780,2375 ; v2(1878.1,1521) C16.2@1878.1,1555 ; L4.1@2195,515 v2(2229.5,515) ; C44.2@2195,615 2209.03,615 v2(2229.03,595) ; SB15.1@2195,675 2205,675 2220,690 v2(2234,690) ; 2260.08,682.5 C45.2@2323.1,682.5 ; 2323.1,644.98 C45.2@2323.1,682.5 ; 2323.1,720.02 C45.2@2323.1,682.5 ; C15.2@2385,1565 v2(2385,1605) ; 2386.12,682.5 C45.2@2323.1,682.5 ; 2405.56,715.55 U10.1@2449.08,715.55 ; 2449.08,743.57 U10.1@2449.08,715.55 ; v2(2462,1611) 2464,1613 2464,1634 C13.2@2490,1660 2505,1645 2505,1614 v2(2503,1612) ; 2475.08,815 C37.2@2508.1,815 ; v2(2477,1797) 2477,1764 2490,1751 C8.2@2490,1750 2509,1769 v2(2509,1797) ; 2492.6,715.55 U10.1@2449.08,715.55 ; C14.2@2505,1575 2537,1607 v2(2537,1612) ; C7.2@2505,1835 v2(2505,1872) ; 2508.1,776.98 C37.2@2508.1,815 ; 2508.1,853.02 C37.2@2508.1,815 ; 2541.12,815 C37.2@2508.1,815 ; v2(2558,1461.5) 2558,1460.5 2593.5,1425 C21.2@2603.1,1425 ; v2(2600,400) R65.1@2638.1,400 2638.1,340.71 T3.2@2635.7,338.31 ; C18.2@2603.1,1505 2603.1,1528.1 v2(2620,1545) ; v2(2605,1240) C25.2@2605,1275 ; v2(2650,1965) 2620,1965 C6.2@2600,1985 2620,2005 v2(2650,2005) ; 2679.19,50.4 CN8.8@2714.71,50.4 2714.71,95.92 ; v2(2744.24,1750.91) 2745,1750.91 2745,1751.67 2773.33,1751.67 2800,1725 C10.2@2800,1710 ; 2759.51,175.6 CN8.7@2788.53,175.6 2788.53,136.08 ; v2(2795,325) D5.2@2843.65,325 ; v2(2833.1,1122.9) C26.2@2833.1,1160 ; C11.1@2853.1,1710 v2(2853.1,1765) ; v2(2898.1,1121.9) C27.2@2898.1,1160 ; C9.1@2927.1,1712 v2(2927.1,1765) ; D5.5@2938.13,325 v2(2982,325) ; 2967.67,136.08 CN8.6@2967.67,175.6 2996.69,175.6 ; C12.2@2993.1,1710 v2(3027,1743.9) ; C28.2@2998.1,1160 3004.1,1154 v2(3031.1,1154) ; 3041.49,95.92 CN8.9@3041.49,50.4 3077.01,50.4 ; R20.1@3055,1710 v2(3086,1741) ; v2(3143.1,1558) 3143.1,1536.9 C17.2@3165,1515 ; C3.2@3153.1,2225 3153.1,2263.1 v2(3165,2275) ; C22.2@3165,1410 3194.74,1410 v1(3197.74,1407) ; U14.2@3213.1,357.76 3213.1,320 C54.2@3238.1,295 v2(3238.1,251.1) ; v2(3415,1005) R50.1@3415,1058.1 ; v2(3415,1339) U7.4@3415,1401.4 ; C4.2@3458.1,2160 v2(3458.1,2204.1) ; v2(3580,1075) C29.1@3580,1118.1 v2(3626.9,1118.1) ; 3595,735.98 C40.2@3595,755 ; 3595,774.02 C40.2@3595,755 ; v2(3608,1519) 3625,1502 C19.1@3625,1483.1 ; U3.4@3608.1,1732.28 v2(3608.1,1801.1) ; 3610,430.98 C42.2@3610,450 ; 3610,469.02 C42.2@3610,450 ; 3614.02,755 C40.2@3595,755 ; 3629.02,450 C42.2@3610,450 ; v2(3856,1375) C23.1@3895,1375 ; v2(3856,1435) C20.1@3894.1,1435 ; v2(3860,1320) C24.2@3895,1320 ; v2(3860,1530) 3895,1495 R31.1@3899.1,1495 ; 3878.1,725.98 C41.2@3878.1,745 ; 3878.1,764.02 C41.2@3878.1,745 ; 3885,440.98 C43.2@3885,460 ; 3885,479.02 C43.2@3885,460 ; 3897.12,745 C41.2@3878.1,745 ; R30.1@3899.1,1550 v2(3899.1,1585) ; 3904.02,460 C43.2@3885,460 ; R49.2@3905,1065 v2(3935,1095) ; CN4.5@4125,1995 v2(4125,2040) ; v2(4140,940) C35.2@4180,940 ; v2(4140,1005) C33.2@4180,1005 ; R17.2@4150,1715 v2(4150,1755) ; CN4.3@4225,1995 v2(4225,2035) ; v2(4255,110) LD8.2@4288.1,110 ; R48.1@4260,1065 4265,1065 v2(4295,1095) ; R22.1@4265,1710 4265,1725 v2(4290,1750) ; v2(4280,980) U9.2@4327.76,980 ; 4465.98,1090 C31.2@4490,1090 ; 4490,1115.52 C31.2@4490,1090 ; LD5.1@4497.63,214.06 v2(4497.63,265) ; 4514.02,1090 C31.2@4490,1090 ; 4530.98,1090 C32.2@4555,1090 ; v2(4555,900) C36.2@4555,940 ; 4555,1115.52 C32.2@4555,1090 ; R34.2@4573.1,1430 v2(4573.1,1465) ; 4579.02,1090 C32.2@4555,1090 ; C46.2@4653.1,615 v2(4653.1,661.9) ; v2(4695,870) C34.2@4735,870 ; v2(4703.1,410) C51.1@4703.1,450 ; U22.2@4807.24,1260 v2(4855,1260) ; R33.1@4808.1,1420 v2(4808.1,1465) ; v2(4870,1065) C30.1@4870,1100 ; 4916.43,1358.43 CN5.9@4954.71,1358.43 ; 4917.19,1161.57 CN5.8@4954.71,1161.57 ; 4954.71,1124.05 CN5.8@4954.71,1161.57 ; 4954.71,1395.95 CN5.9@4954.71,1358.43 ; 4992.23,1161.57 CN5.8@4954.71,1161.57 ; 4992.23,1358.43 CN5.9@4954.71,1358.43 ; 5015.49,1122.2 CN5.6@5061.01,1122.2 5061.01,1090.68 ; 5015.49,1397.8 CN5.7@5061.01,1397.8 5061.01,1429.32
  L2_GND w8: 2701,1425 v3(2779.67,1425) ; 2762,1512 2770.26,1503.74 v3(2779.67,1503.74) ; 2806,1591 2817,1580 2817,1544.37 2818.86,1542.51 2818.86,1523.61 v3(2819.04,1523.43) ; v3(2858.41,1523.43) 2862,1527.02 2862,1567
  L2_GND w9: v3(2956.84,1326.76) 2958,1325.6 2958,1315.32
  L2_GND w20: 2679.19,50.4 CN8.8@2714.71,50.4 2714.71,95.92 ; 2759.51,175.6 CN8.7@2788.53,175.6 ; 2788.53,136.08 CN8.7@2788.53,175.6 ; 2788.53,215.12 CN8.7@2788.53,175.6 ; 2817.55,175.6 CN8.7@2788.53,175.6 ; 2938.65,175.6 CN8.6@2967.67,175.6 ; 2967.67,136.08 CN8.6@2967.67,175.6 ; 2967.67,215.12 CN8.6@2967.67,175.6 ; 2996.69,175.6 CN8.6@2967.67,175.6 ; 3041.49,95.92 CN8.9@3041.49,50.4 3077.01,50.4 ; 3224.08,2515 CN9.3@3258.1,2515 ; 3258.1,2480.98 CN9.3@3258.1,2515 ; 3258.1,2549.02 CN9.3@3258.1,2515 ; 3292.12,2515 CN9.3@3258.1,2515 ; 3816.98,1230 JP10.2@3855,1230 ; 3855,1191.98 JP10.2@3855,1230 ; 3855,1268.02 JP10.2@3855,1230 ; 3893.02,1230 JP10.2@3855,1230 ; 3939.71,2273.42 CN2.5@3973.73,2273.42 ; 3973.73,2239.4 CN2.5@3973.73,2273.42 ; 3973.73,2307.44 CN2.5@3973.73,2273.42 ; 4007.75,2273.42 CN2.5@3973.73,2273.42 ; 4018.45,2352.16 CN2.16@4052.47,2352.16 ; 4052.47,2318.14 CN2.16@4052.47,2352.16 ; 4052.47,2386.18 CN2.16@4052.47,2352.16 ; 4086.49,2352.16 CN2.16@4052.47,2352.16 ; 4580.08,1840 CN3.5@4618.1,1840 ; 4618.1,1801.98 CN3.5@4618.1,1840 ; 4618.1,1878.02 CN3.5@4618.1,1840 ; 4656.12,1840 CN3.5@4618.1,1840 ; 4680.08,1840 CN3.11@4718.1,1840 ; 4718.1,1801.98 CN3.11@4718.1,1840 ; 4718.1,1878.02 CN3.11@4718.1,1840 ; 4756.12,1840 CN3.11@4718.1,1840 ; 4864.08,1580 CN14.3@4898.1,1580 ; 4875.08,320 CN7.3@4913.1,320 ; 4898.1,1545.98 CN14.3@4898.1,1580 ; 4898.1,1614.02 CN14.3@4898.1,1580 ; 4913.1,281.98 CN7.3@4913.1,320 ; 4913.1,358.02 CN7.3@4913.1,320 ; 4917.19,1161.57 CN5.8@4954.71,1161.57 ; 4917.19,1358.43 CN5.9@4954.71,1358.43 ; 4932.12,1580 CN14.3@4898.1,1580 ; 4951.12,320 CN7.3@4913.1,320 ; 4954.71,1124.05 CN5.8@4954.71,1161.57 ; 4954.71,1199.09 CN5.8@4954.71,1161.57 ; 4954.71,1320.91 CN5.9@4954.71,1358.43 ; 4954.71,1395.95 CN5.9@4954.71,1358.43 ; 4992.23,1161.57 CN5.8@4954.71,1161.57 ; 4992.23,1358.43 CN5.9@4954.71,1358.43 ; 5015.49,1122.2 CN5.6@5061.01,1122.2 ; 5015.49,1397.8 CN5.7@5061.01,1397.8 ; 5061.01,1090.68 CN5.6@5061.01,1122.2 ; 5061.01,1153.72 CN5.6@5061.01,1122.2 ; 5061.01,1366.28 CN5.7@5061.01,1397.8 ; 5061.01,1429.32 CN5.7@5061.01,1397.8
  L5_GND w10: v7(2845,1660) 2845,1680 v5(2854,1689) 2865,1678 v7(2865,1660)
  L5_GND w20: 2679.19,50.4 CN8.8@2714.71,50.4 2714.71,95.92 ; 2759.51,175.6 CN8.7@2788.53,175.6 ; 2788.53,136.08 CN8.7@2788.53,175.6 ; 2788.53,215.12 CN8.7@2788.53,175.6 ; 2817.55,175.6 CN8.7@2788.53,175.6 ; 2938.65,175.6 CN8.6@2967.67,175.6 ; 2967.67,136.08 CN8.6@2967.67,175.6 ; 2967.67,215.12 CN8.6@2967.67,175.6 ; 2996.69,175.6 CN8.6@2967.67,175.6 ; 3041.49,95.92 CN8.9@3041.49,50.4 3077.01,50.4 ; 3224.08,2515 CN9.3@3258.1,2515 ; 3258.1,2480.98 CN9.3@3258.1,2515 ; 3258.1,2549.02 CN9.3@3258.1,2515 ; 3292.12,2515 CN9.3@3258.1,2515 ; 3816.98,1230 JP10.2@3855,1230 ; 3855,1191.98 JP10.2@3855,1230 ; 3855,1268.02 JP10.2@3855,1230 ; 3893.02,1230 JP10.2@3855,1230 ; 3939.71,2273.42 CN2.5@3973.73,2273.42 ; 3973.73,2239.4 CN2.5@3973.73,2273.42 ; 3973.73,2307.44 CN2.5@3973.73,2273.42 ; 4007.75,2273.42 CN2.5@3973.73,2273.42 ; 4018.45,2352.16 CN2.16@4052.47,2352.16 ; 4052.47,2318.14 CN2.16@4052.47,2352.16 ; 4052.47,2386.18 CN2.16@4052.47,2352.16 ; 4086.49,2352.16 CN2.16@4052.47,2352.16 ; 4580.08,1840 CN3.5@4618.1,1840 ; 4618.1,1801.98 CN3.5@4618.1,1840 ; 4618.1,1878.02 CN3.5@4618.1,1840 ; 4656.12,1840 CN3.5@4618.1,1840 ; 4680.08,1840 CN3.11@4718.1,1840 ; 4718.1,1801.98 CN3.11@4718.1,1840 ; 4718.1,1878.02 CN3.11@4718.1,1840 ; 4756.12,1840 CN3.11@4718.1,1840 ; 4864.08,1580 CN14.3@4898.1,1580 ; 4875.08,320 CN7.3@4913.1,320 ; 4898.1,1545.98 CN14.3@4898.1,1580 ; 4898.1,1614.02 CN14.3@4898.1,1580 ; 4913.1,281.98 CN7.3@4913.1,320 ; 4913.1,358.02 CN7.3@4913.1,320 ; 4917.19,1161.57 CN5.8@4954.71,1161.57 ; 4917.19,1358.43 CN5.9@4954.71,1358.43 ; 4932.12,1580 CN14.3@4898.1,1580 ; 4951.12,320 CN7.3@4913.1,320 ; 4954.71,1124.05 CN5.8@4954.71,1161.57 ; 4954.71,1199.09 CN5.8@4954.71,1161.57 ; 4954.71,1320.91 CN5.9@4954.71,1358.43 ; 4954.71,1395.95 CN5.9@4954.71,1358.43 ; 4992.23,1161.57 CN5.8@4954.71,1161.57 ; 4992.23,1358.43 CN5.9@4954.71,1358.43 ; 5015.49,1122.2 CN5.6@5061.01,1122.2 ; 5015.49,1397.8 CN5.7@5061.01,1397.8 ; 5061.01,1090.68 CN5.6@5061.01,1122.2 ; 5061.01,1153.72 CN5.6@5061.01,1122.2 ; 5061.01,1366.28 CN5.7@5061.01,1397.8 ; 5061.01,1429.32 CN5.7@5061.01,1397.8
  BOTTOM w6: v2(515.63,1625) 525.38,1634.75 CN13.6@525.38,1664.25 ; CN13.3@556.88,1768.59 556.88,1753.75 565.63,1745 580.63,1745 588.38,1752.75 CN13.1@588.38,1768.59 588.38,1780 593.38,1785 615,1785 v2(620,1780) ; CN13.10@588.38,1664.25 605.75,1664.25 v2(615,1655)
  BOTTOM w9: v2(850,1179.53) U21.8@898.74,1179.53 ; v2(974.14,1030.41) 981.42,1023.13 U21.47@981.42,978.74 ; U18.28@1160.28,2019.84 1193.83,2019.84 v2(1200.22,2026.23) ; U21.35@1241.26,1061.42 1281.42,1061.42 C101.2@1305,1085 ; U12.B2@3577.87,557.13 3597.87,557.13 3609.5,545.5 3617.5,545.5 ; v6(3820,587) 3831.13,575.87 U13.C1@3839.13,575.87 ; U13.D2@3854.87,591.62 3870,606.75 v2(3870,610)
  BOTTOM w10: v2(1067.5,1514) 1076,1514 1094.71,1495.29 U20.4@1112.01,1495.29 ; v2(1158.58,1268.58) U21.23@1158.58,1321.26 ; U13.B2@3854.87,560.13 3856,559 3899,559 v2(3904,554)
  BOTTOM w14: v2(1064,1677) 1077.29,1690.29 U19.4@1112.01,1690.29
  BOTTOM w20: v2(344,2385) C63.2@378.1,2385 ; U17.2@506.07,2411.34 556.34,2411.34 v2(570,2425) ; v2(574,1916) 603,1887 R89.2@603,1881 ; v2(665,1310) 665,1350 C91.2@680,1365 695,1350 v2(695,1310) ; v2(670,1615) 680,1625 C82.2@710,1625 ; v2(710,1020) C102.2@755,1020 ; v2(710,1080) R109.1@755,1080 ; C94.2@755,1260 v2(755,1295) ; SB22.1@770,1510 v2(810,1510) ; C80.2@770,1675 v2(810,1675) ; v2(785,1230) C99.1@815,1200 ; CN17.9@786.6,593.35 786.6,638.6 v2(796,648) ; R104.2@905,1455 v2(940,1455) ; CN17.6@918.49,593.35 918.49,638.49 v2(930,650) ; v2(940,1521.9) R98.2@975,1521.9 ; v2(940,1576.9) C85.1@975,1576.9 ; C103.2@965,835 v2(995,865) ; R113.2@1025,835 v2(1055,865) 1055,860 R112.2@1080,835 ; R80.1@1035,2385 v2(1080,2385) ; v2(1125,1730) R91.1@1125,1770 ; v2(1160,2385) C62.2@1200,2385 ; R83.1@1210,2240 v2(1210,2277.9) ; v2(1270,1290) 1278.1,1290 C93.2@1303.1,1265 ; C101.2@1305,1085 v2(1305,1130) ; C74.2@1305,1955 1320,1955 v2(1345,1980) ; C73.2@1305,2025 v2(1350,2025) ; C71.1@1305,2075 v2(1350,2075) ; v2(1420,1319) C90.2@1420,1365 ; C83.1@1420,1611.9 1420,1610 v2(1450,1580) C84.2@1480,1610 ; R110.1@1720,975 1720,1010 v2(1730,1020) ; v2(1760,1995) 1765,1990 R84.1@1765,1950 ; R106.1@1765,1265 v2(1765,1305) ; C104.2@1855,745 1880,745 v2(1890,755) ; C60.2@2038.1,2550 2072,2550 v2(2080,2542) ; v2(2323.1,2542) 2323.1,2510 C61.2@2338.1,2495 2355,2511.9 v2(2355,2542) ; v2(2440,370) 2453.1,356.9 CN15.7@2453.1,295 ; CN15.6@2553.1,430 v2(2553.1,511.9) ; v2(2833.1,1122.9) C98.2@2833.1,1160 ; v2(2898.1,1121.9) C97.2@2898.1,1160 ; C95.2@3018.1,1225 v2(3053,1225) ; v2(3083.1,1091.9) C100.2@3083.1,1145 ; v2(3113.1,2252) CN10.7@3113.1,2330 ; C89.2@3165,1410 3194.74,1410 v1(3197.74,1407) ; C92.2@4054.1,1370 v2(4101,1370) ; v2(4145,1600) 4164.1,1580.9 C86.2@4164.1,1555 ; C96.2@4284.1,1215 4284.1,1248.1 v2(4301,1265) ; v2(4346,1465) 4356,1455 C87.2@4386,1455 ; C105.2@4798,1262 4853,1262 v2(4855,1260)
  other v1: 1010,1955 1065,1955 1120,1955 1010,2010 1065,2010 1120,2010 1010,2065 1065,2065 1120,2065
  other v2: 3930,420 3687,430 3651,431 3930,450 3687,460 3651,461 3930,481 3634,529 2920,580 2979,582 3919,707 3630,719 3921,735 3630,750 3922,767 3630,780 2882,822 2396,863 2425,863 2535,865 2506.1,867.52 2882,890 4600,1085 4600,1115 3741,1378 2935,1880 2815,1885 1374,2343 546,2345 475,2470 1300,2472 1368,2520 541,2523 1300,2568
  other v3: 2858.41,1326.57 2779.67,1346.26 2976.53,1503.74 2897.79,1523.43 2956.84,1523.43
IDD_MEAS: C84.1 R102.1 U21.25 | length 492.6
  TOP w5: v1(1295,1230) 1295,1275 1480,1460 v1(1480,1515.5)
  BOTTOM w5: U21.25@1241.26,1258.27 1264.18,1258.27 1292.45,1230 v1(1295,1230) ; R102.1@1480,1485 v1(1480,1515.5) C84.1@1480,1550
JOY_DOWN: B2.3 U5.A1 | length 4801.8
  TOP w5: B2.3@563.7,183.27 610,229.57 v1(610,390) ; v1(2647,2136) 2683.69,2136 2819.69,2000 2925.69,2000 3045.69,1880 3131.22,1880 3182.5,1828.72 3182.5,1641.78 3136.22,1595.5 3062.72,1595.5 3017.22,1550 3003.1,1550 U5.A1@2996.21,1543.11
  L3_SIG w4: v1(610,390) 625,405 625,787.44 847.56,1010 1167.56,1010 1210,1052.44 1210,1555 1235,1580 1235,1891.22 1285,1941.22 1362.56,1941.22 1603.34,2182 2536,2182 2558,2160 2623,2160 v1(2647,2136)
JOY_LEFT: B2.1 U5.B1 | length 4748
  TOP w5: B2.1@485.75,261.22 485.75,261.69 520.56,296.5 v1(530,296.5) ; v1(2571,2138) 2593.5,2115.5 2682.97,2115.5 2813.47,1985 2919.47,1985 3039.47,1865 3125,1865 3167.5,1822.5 3167.5,1648 3130,1610.5 3056.5,1610.5 3011,1565 2995,1565 2976.53,1546.53 U5.B1@2976.53,1543.11
  L3_SIG w4: v1(530,296.5) 571.5,296.5 640,365 640,781.22 853.78,995 1173.78,995 1225,1046.22 1225,1541.98 1252.5,1569.48 1252.5,1887.5 1291.22,1926.22 1368.78,1926.22 1612.56,2170 2528,2170 2560,2138 v1(2571,2138)
JOY_RIGHT: B2.4 U5.M5 | length 3778.6
  TOP w5: B2.4@736.31,355.88 v1(780,399.57)
  L2_GND w3.5: v5(2703.02,1502.06) 2718.98,1486.1 2718.98,1471.98 2727.66,1463.3 2740.09,1463.3 2742.79,1466 2778.04,1466 v3(2779.67,1464.37)
  L3_SIG w4: v1(780,399.57) 667,512.57 667,735 877,945 946,945 998.5,892.5 1066.5,892.5 1087,872 1658,872 1775,989 1775,1096 1863,1184 1863,1222 1785,1300 1785,1730 1855,1800 v1(1880,1800)
  L5_GND w3.5: v7(2703.02,1487.02) v5(2703.02,1502.06)
  BOTTOM w5: v1(1880,1800) 1900,1780 2015,1780 2037.5,1802.5 2397.5,1802.5 2585,1615 2585,1550 2647.98,1487.02 v7(2703.02,1487.02)
JOY_SEL: B2.2 U5.E1 | length 4409.2
  TOP w5: B2.2@524.73,222.25 570,267.52 v1(570,270) ; v1(2533.92,2112.08) 2562,2084 2668.5,2084 2800,1952.5 2909.53,1952.5 3000,1862.03 3000,1785 2954,1739 2954,1631 2917.47,1594.47 U5.E1@2917.47,1543.11
  L3_SIG w4: v1(570,270) 655,355 655,775 860,980 1180,980 1240,1040 1240,1540 1282.5,1582.5 1282.5,1797.5 1631,2146 2500,2146 v1(2533.92,2112.08)
JOY_UP: B2.6 U5.C11 | length 3221
  TOP w5: B2.6@658.36,433.83 745,520.47 745,640 v1(785,680)
  L2_GND w3.5: v3(2956.84,1346.26) 2963.44,1346.26 2966.78,1342.92 2966.78,1342.22 2972.49,1336.51 2973.19,1336.51 2973.38,1336.32 2999.64,1336.32 3015.96,1320 3030,1320
  L2_GND w5: 3030,1320 3057.22,1320 3069.48,1307.74 v5(3069.83,1307.74)
  L3_SIG w4: v1(785,680) 875,680 945,750 1262.92,750 1296.92,784 1804,784 1868,848 1918.98,848 1933.36,862.38 1989.52,862.38 2003.9,848 2049.02,848 2057.02,840 2080,840 2135,785 2771,785 2838,852 2838,895 3012.5,1069.5 3031.5,1069.5 3115,1153 3115,1270 3077.26,1307.74 v5(3069.83,1307.74)
LCD_BL: R76.1 R77.1 U5.A12 U15.7 | length 2847.8
  TOP w3.5: 3126,1326.57 3126.84,1325.73
  TOP w5: U5.A12@2996.21,1326.57 3126,1326.57 ; 3126.84,1325.73 3190.57,1262 3298,1262 v1(3311,1275)
  TOP w10: R77.1@1980,130 1955,155 R76.1@1955,190 1988.1,190 v1(1998.1,200) ; v1(1998.1,280) 1999.3,281.2 U15.7@2035.03,281.2
  L3_SIG w4: v1(1998.1,280) 1998.1,335.1 2214.5,551.5 2611.5,551.5 2745,418 3003,418 3196,611 3257,611 3360,714 3360,1020 3311,1069 v1(3311,1275)
  L3_SIG w10: v1(1998.1,200) v1(1998.1,280)
LCD_NE: CN6.22 R52.1 U5.F7 | length 1441.6
  TOP w5: CN6.22@2044.44,750.65 2094.27,750.65 R52.1@2135,791.38 2220,876.38 v1(2220,935)
  L3_SIG w3.5: v4(2897.79,1425) 2892,1425 2882.25,1415.25 2874.25,1415.25 2868.35,1409.35 2868.35,1344.87 2915.22,1298 2926,1298
  L3_SIG w4: v1(2220,935) 2291,935 2339.5,983.5 2788.5,983.5 2947.5,1142.5 2947.5,1276.5 2926,1298
LCD_OE: CN6.19 U4.A2 U5.C7 | length 3032.6
  TOP w4: v6(2080,1675) 2088.81,1666.19 U4.A2@2088.81,1653.35
  TOP w5: v1(1895,815) 1895,805 1913.91,786.09 CN6.19@1930.26,786.09
  L2_GND w3.5: v3(2956.84,1425) 2966.78,1415.06 2980.57,1415.06 2981.38,1414.25 3034.03,1414.25 3036.78,1417 v5(3038,1417)
  L5_GND w3.5: v5(3038,1417) v7(3038,1435)
  BOTTOM w4: 2005,1637.44 2017.56,1650 2049,1650 2074,1675 v6(2080,1675)
  BOTTOM w5: v1(1895,815) 1878,832 1878,937 1858,957 1858,984 1880,1006 1880,1473.1 1915,1508.1 1915,1547.44 2005,1637.44 ; v6(2080,1675) 2086.5,1668.5 2086.5,1660.5 2093,1654 2229,1654 2232,1651 2232,1634 2237,1629 2245.62,1629 2250.62,1634 2250.62,1661 2255.62,1666 2265.62,1666 2270.62,1661 2270.62,1603 2275.62,1598 2287,1598 2292,1603 2292,1624 2297,1629 2307,1629 2312,1624 2312,1562 2317,1557 2356,1557 2361,1552 2361,1530 2366,1525 2378,1525 2383,1530 2383,1557 2388,1562 2399.5,1562 2404.5,1557 2404.5,1482 2409.5,1477 2420.04,1477 2425.04,1482 2425.04,1551 2430.04,1556 2440.04,1556 2445.04,1551 2445.04,1454 2450.04,1449 2460.16,1449 2465.16,1454 2465.16,1542 2470.16,1547 2480.16,1547 2485.16,1542 2485.16,1451 2490.16,1446 2500.16,1446 2505.16,1451 2505.16,1537 2510.16,1542 2520.16,1542 2525.16,1537 2525.16,1486.84 2530,1482 2576,1482 2581,1477 2581,1452 2586,1447 2621,1447 2625,1443 2948,1443 2957,1452 3020,1452 3037,1435 v7(3038,1435)
LCD_PWR_ON: R115.2 T11.3 T12.3 U5.H1 | length 4164.5
  TOP w5: U5.H1@2858.41,1543.11 v4(2858.45,1592) v4(2858.45,1592)
  L3_SIG w4: v1(725,820) 870,965 1095,965 1159,901 1414,901 1455,942 1455,1007 1530,1082 1530,1905 1708,2083 2053.04,2083 2085.04,2051 2355.06,2051 2425.06,1981 2556.18,1981 2616.18,1921 2651.98,1921 2838.99,1733.99 2848.93,1733.99 2871.84,1734 2897,1708.84 2897,1624.21 2864.79,1592 v4(2858.45,1592)
  BOTTOM w5: T12.3@335.5,837.24 342.74,830 R115.2@400,830 400,905 420,925 555,925 580.5,899.5 T11.3@580.5,837.24 707.76,837.24 v1(725,820)
LCD_RST: CN6.23 R117.2 U21.20 | length 1784.7
  TOP w5: v1(1039,1220) 999,1180 945,1180 915,1150 915,1030 990,955 1620,955 1650,925 1650,707.5 1680,677.5 1796.5,677.5 1849.5,730.5 1896.55,730.5 1904.89,738.84 CN6.23@1930.26,738.84 1958.68,738.84 1959.84,740 v1(1961.26,740)
  BOTTOM w5: v1(1039,1220) 1050,1220 1099.53,1269.53 U21.20@1099.53,1321.26 ; R117.2@1930,745 1954.84,745 1959.84,740 v1(1961.26,740)
LCD_TE: CN6.2 U5.D12 | length 1334.8
  TOP w5: CN6.2@2044.44,986.87 2072.07,986.87 v1(2090.47,968.47)
  L2_GND w3.5: v3(2937.16,1326.57) 2937.16,1307.09 2947.5,1296.75 2947.5,1282.5 2960,1270 v5(2961,1270)
  L3_SIG w3.5: v5(2961,1270) 2964.06,1270 2984,1250.06
  L3_SIG w4: v1(2090.47,968.47) 2129.47,929.47 2177.53,929.47 2270,837 2570,837 2692,959 2798.98,959 2971.5,1131.52 2971.5,1203.5 2986,1218 2986,1248.06 2984,1250.06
